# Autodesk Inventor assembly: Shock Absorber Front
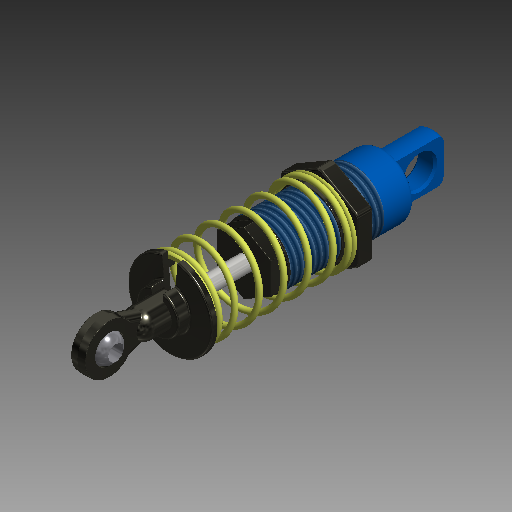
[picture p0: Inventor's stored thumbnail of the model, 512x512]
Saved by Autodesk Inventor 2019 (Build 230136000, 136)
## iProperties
Shininess: 50.0
Compacted: True
Length Units: 11272
Angle Units: 11279
Time Units: 11290
Mass Units: 11286
Length Display Precision: 4
Angle Display Precision: 2
Company: Autodesk
Created: 2000-03
Part Number: Shock Absorber Front
Project: Inventor Samples
Document SubType Name: Assembly
Designer: Autodesk, Inc.
Mass: 9.15356 g
Surface Area: 77.6242 cm^2
Volume: 3.97768 cm^3
Density: 2.30123 g/cm^3
Density: 0.0
Volumn: 0.0
Area: 0.0
PropertySet Name: Model Information
Control State: 0
Master: False
Checked Out: False
Checked Out Date: 2018-05-30
Last Check In Date: 2018-05-30
Title: 1.3 SHOCK
Author: Autodesk, Inc.
Revision Number: A
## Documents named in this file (5)
- C:\Users\itools\Desktop\autodesk_inventor_2018_samples\Models\Assemblies\Suspension\Components\Shock Absorber Front.iam
- C:\Users\itools\Desktop\autodesk_inventor_2018_samples\Models\Assemblies\Suspension\Components\Shock Spring Adjustment Nut.ipt
- C:\Users\itools\Desktop\autodesk_inventor_2018_samples\Models\Assemblies\Suspension\Components\Suspension_Spring.ipt
- C:\Users\itools\Desktop\autodesk_inventor_2018_samples\Models\Assemblies\Suspension\Components\Shock Body.iam
- C:\Users\itools\Desktop\autodesk_inventor_2018_samples\Models\Assemblies\Suspension\Components\Shock Strut.iam
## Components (4 placed, 4 different names)
1. Shock Spring Adjust Nut.ipt:1 — Mate MID
2. Suspension_Spring:1 — Mate MID
3. Shock Body:1 [sub-assembly] — Mate:20, Angle:7, Mate OPEN, Mate CLOSED
4. Shock Strut:1 [sub-assembly] — Mate:20, Angle:7, Mate OPEN, Mate CLOSED
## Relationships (5: Mate 4, Angle 1)
- Mate MID: Shock Spring Adjust Nut.ipt:1 ↔ Suspension_Spring:1
- Mate:20: Shock Body:1 ↔ Shock Strut:1
- Angle:7: Shock Body:1 ↔ Shock Strut:1
- Mate OPEN: Shock Body:1 ↔ Shock Strut:1
- Mate CLOSED: Shock Body:1 ↔ Shock Strut:1
